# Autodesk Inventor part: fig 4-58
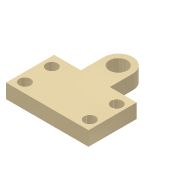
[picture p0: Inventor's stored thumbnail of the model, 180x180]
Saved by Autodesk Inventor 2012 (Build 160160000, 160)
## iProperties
Created: 2004-05
Part Number: fig 4-58
Document SubType Name: Modeling
Designer: CADCIM Technologies
Manufacturer: Standard
Standards Organization: Custom
Density: 1 g/cm^3
Material: Default
Author: CADCIM Technologies
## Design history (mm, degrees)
sketch "Sketch1"
  geometry: L1 (39.729, 55.62)-(39.729, 42.054); L2 (39.729, 42.054)-(23.837, 42.054); L3 (23.837, 42.054)-(23.837, 13.516); L4 (23.837, 13.516)-(72.804, 13.516); L5 (72.804, 13.516)-(72.804, 42.054); L6 (72.804, 42.054)-(56.912, 42.054); L7 (56.912, 42.054)-(56.912, 55.62); C1 r 3.354 at (29.212, 35.336); C2 r 3.354 at (29.212, 19.383); C3 r 3.354 at (67.7, 35.336); C4 r 3.354 at (67.7, 19.383); C5 r 5.297 at (48.32, 55.62); A1 r 8.592 centre (48.32, 55.62) between (56.912, 55.62) and (39.729, 55.62)
  constraints: 14 end point, 6 centre point, 4 parallel, 2 equal length, 2 horizontal alignment, 2 point on circle, 2 tangent, 2 vertical alignment, 1 coincident, 1 collinear, 1 perpendicular, 1 vertical
extrude "Extrusion1" new body sketch "Sketch1" distance "d0" = 8.5; taper "d1" = 0 deg
body "Solid1"
